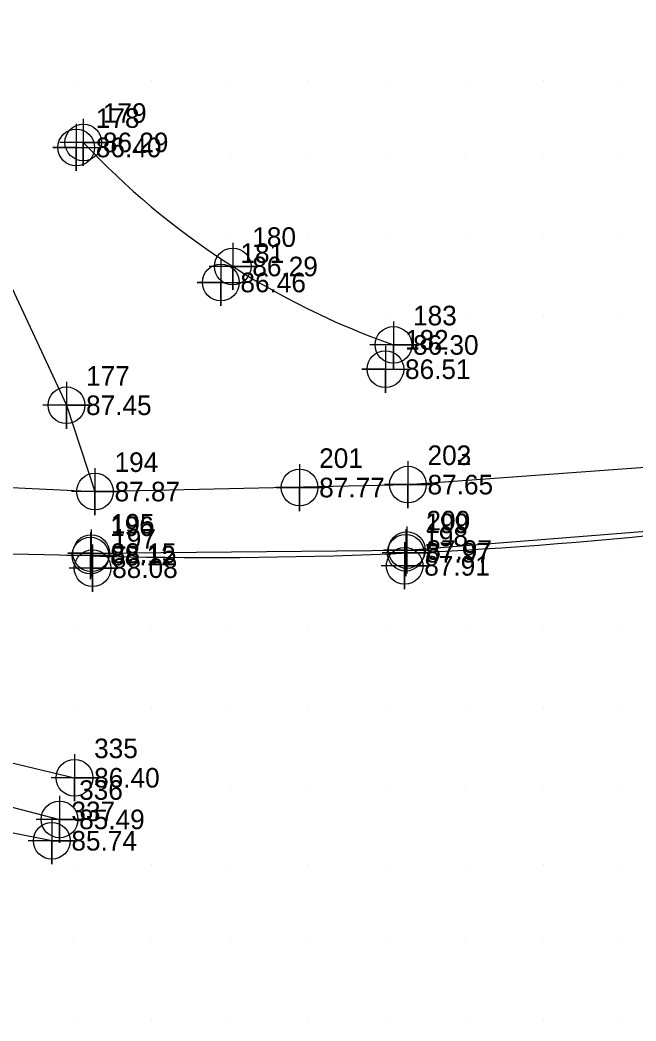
# Model space of a CAD drawing. Extents: x 1988140 to 1988766, y 249950 to 250250.
# Drawn here: x 1988293.2 to 1988371.8, y 249980 to 250107.7 of the extents above; entities that cross this region are included whole.
import ezdxf

# ---------------------------------------------------------------- set-up
doc = ezdxf.new("R2010")
doc.units = 0
for name, color, linetype in [('Exist DTM Breakline', 7, 'Continuous'), ('Exist DTM Breakline Cogo Elevation', 7, 'Continuous'), ('Exist DTM Breakline Cogo Number', 7, 'Continuous'), ('Exist DTM Breakline Cogo Point CELL', 7, 'Continuous'), ('Exist DTM Crownline', 7, 'Continuous'), ('Exist DTM Crownline Cogo Elevation', 7, 'Continuous'), ('Exist DTM Crownline Cogo Number', 7, 'Continuous'), ('Exist DTM Crownline Cogo Point CELL', 7, 'Continuous'), ('Exist DTM QL2 LIDAR Elevation Point', 7, 'Continuous'), ('Exist DTM Regular Point CELL', 7, 'Continuous'), ('Exist DTM Regular Point Cogo Elevation', 7, 'Continuous'), ('Exist DTM Regular Point Cogo Number', 7, 'Continuous'), ('Exist Roads EOP', 7, 'Continuous'), ('Exist Roads EOP Cogo Elevation', 7, 'Continuous'), ('Exist Roads EOP Cogo Number', 7, 'Continuous'), ('Exist Roads EOP Cogo Point CELL', 7, 'Continuous'), ('Exist Roads EOT', 7, 'Continuous'), ('Exist Roads EOT Cogo Elevation', 7, 'Continuous'), ('Exist Roads EOT Cogo Number', 7, 'Continuous'), ('Exist Roads EOT Cogo Point CELL', 7, 'Continuous')]:
    doc.layers.add(name, color=color, linetype=linetype)

msp = doc.modelspace()

# ---------------------------------------------------------------- linework, layer by layer
at = {"layer": 'Exist DTM Breakline'}
for points in [[(1988182.6136, 250035.5158), (1988182.9813, 250039.2171), (1988184.903, 250041.4732), (1988219.3187, 250033.3718), (1988254.9783, 250021.8401), (1988300.1272, 250011.0374)], [(1988185.4236, 250038.4105), (1988216.1279, 250028.952), (1988254.719, 250017.0301), (1988298.2155, 250005.7241)], [(1988297.226, 250002.9987), (1988255.3705, 250011.301), (1988214.5049, 250025.8516), (1988182.6136, 250035.5158)]]:
    msp.add_lwpolyline(points, dxfattribs=at)
at = {"layer": 'Exist DTM Breakline Cogo Point CELL'}
for points in [[(1988300.1272, 250014.0374), (1988300.1272, 250008.0374), (1988300.1272, 250011.0374), (1988303.1272, 250011.0374), (1988297.1272, 250011.0374)], [(1988298.2155, 250008.7241), (1988298.2155, 250002.7241), (1988298.2155, 250005.7241), (1988301.2155, 250005.7241), (1988295.2155, 250005.7241)], [(1988297.226, 250005.9987), (1988297.226, 249999.9987), (1988297.226, 250002.9987), (1988300.226, 250002.9987), (1988294.226, 250002.9987)]]:
    msp.add_lwpolyline(points, dxfattribs=at)
for centre in [(1988300.1272, 250011.0374), (1988298.2155, 250005.7241), (1988297.226, 250002.9987)]:
    msp.add_circle(centre, 2.344, dxfattribs=at)
at = {"layer": 'Exist DTM Crownline'}
for p, q in [((1988299.095, 250058.5693), (1988302.7374, 250047.561)), ((1988275.108, 250048.9258), (1988302.7374, 250047.561)), ((1988302.7374, 250047.561), (1988342.6848, 250048.4444))]:
    msp.add_line(p, q, dxfattribs=at)
for points in [[(1988218.8793, 250228.6049), (1988245.0113, 250174.1068), (1988268.5227, 250125.7119), (1988280.5459, 250098.297), (1988299.095, 250058.5693)], [(1988342.6848, 250048.4444), (1988378.1968, 250051.0543), (1988417.6158, 250057.1729)]]:
    msp.add_lwpolyline(points, dxfattribs=at)
at = {"layer": 'Exist DTM Crownline Cogo Point CELL'}
for points in [[(1988299.095, 250061.5693), (1988299.095, 250055.5693), (1988299.095, 250058.5693), (1988302.095, 250058.5693), (1988296.095, 250058.5693)], [(1988342.6848, 250051.4444), (1988342.6848, 250045.4444), (1988342.6848, 250048.4444), (1988345.6848, 250048.4444), (1988339.6848, 250048.4444)], [(1988302.7374, 250050.561), (1988302.7374, 250044.561), (1988302.7374, 250047.561), (1988305.7374, 250047.561), (1988299.7374, 250047.561)]]:
    msp.add_lwpolyline(points, dxfattribs=at)
for centre in [(1988299.095, 250058.5693), (1988342.6848, 250048.4444), (1988302.7374, 250047.561)]:
    msp.add_circle(centre, 2.344, dxfattribs=at)
at = {"layer": 'Exist DTM QL2 LIDAR Elevation Point'}
for p, q in [((1988300, 250100), (1988300, 250100)), ((1988310, 250100), (1988310, 250100)), ((1988320, 250100), (1988320, 250100)), ((1988330, 250100), (1988330, 250100)), ((1988340, 250100), (1988340, 250100)), ((1988350, 250100), (1988350, 250100)), ((1988360, 250100), (1988360, 250100)), ((1988370, 250100), (1988370, 250100)), ((1988310, 250090), (1988310, 250090)), ((1988320, 250090), (1988320, 250090)), ((1988330, 250090), (1988330, 250090)), ((1988340, 250090), (1988340, 250090)), ((1988350, 250090), (1988350, 250090)), ((1988360, 250090), (1988360, 250090)), ((1988370, 250090), (1988370, 250090)), ((1988320, 250080), (1988320, 250080)), ((1988330, 250080), (1988330, 250080)), ((1988340, 250080), (1988340, 250080)), ((1988350, 250080), (1988350, 250080)), ((1988360, 250080), (1988360, 250080)), ((1988370, 250080), (1988370, 250080)), ((1988340, 250070), (1988340, 250070)), ((1988350, 250070), (1988350, 250070)), ((1988360, 250070), (1988360, 250070)), ((1988370, 250070), (1988370, 250070)), ((1988370, 250040), (1988370, 250040)), ((1988300, 250030), (1988300, 250030)), ((1988310, 250030), (1988310, 250030)), ((1988320, 250030), (1988320, 250030)), ((1988330, 250030), (1988330, 250030)), ((1988340, 250030), (1988340, 250030)), ((1988350, 250030), (1988350, 250030)), ((1988360, 250030), (1988360, 250030)), ((1988370, 250030), (1988370, 250030)), ((1988300, 250020), (1988300, 250020)), ((1988310, 250020), (1988310, 250020)), ((1988320, 250020), (1988320, 250020)), ((1988330, 250020), (1988330, 250020)), ((1988340, 250020), (1988340, 250020)), ((1988350, 250020), (1988350, 250020)), ((1988360, 250020), (1988360, 250020)), ((1988370, 250020), (1988370, 250020)), ((1988310, 250010), (1988310, 250010)), ((1988320, 250010), (1988320, 250010)), ((1988330, 250010), (1988330, 250010)), ((1988340, 250010), (1988340, 250010)), ((1988350, 250010), (1988350, 250010)), ((1988360, 250010), (1988360, 250010)), ((1988370, 250010), (1988370, 250010)), ((1988300, 250000), (1988300, 250000)), ((1988310, 250000), (1988310, 250000)), ((1988320, 250000), (1988320, 250000)), ((1988330, 250000), (1988330, 250000)), ((1988340, 250000), (1988340, 250000)), ((1988350, 250000), (1988350, 250000)), ((1988360, 250000), (1988360, 250000)), ((1988370, 250000), (1988370, 250000)), ((1988300, 249990), (1988300, 249990)), ((1988310, 249990), (1988310, 249990)), ((1988320, 249990), (1988320, 249990)), ((1988330, 249990), (1988330, 249990)), ((1988340, 249990), (1988340, 249990)), ((1988350, 249990), (1988350, 249990)), ((1988360, 249990), (1988360, 249990)), ((1988370, 249990), (1988370, 249990)), ((1988300, 249980), (1988300, 249980)), ((1988310, 249980), (1988310, 249980)), ((1988320, 249980), (1988320, 249980)), ((1988330, 249980), (1988330, 249980)), ((1988340, 249980), (1988340, 249980)), ((1988350, 249980), (1988350, 249980)), ((1988360, 249980), (1988360, 249980)), ((1988370, 249980), (1988370, 249980))]:
    msp.add_line(p, q, dxfattribs=at)
at = {"layer": 'Exist DTM Regular Point CELL'}
for points in [[(1988342.2631, 250041.0837), (1988342.2631, 250035.0837), (1988342.2631, 250038.0837), (1988345.2631, 250038.0837), (1988339.2631, 250038.0837)], [(1988302.4323, 250040.7842), (1988302.4323, 250034.7842), (1988302.4323, 250037.7842), (1988305.4323, 250037.7842), (1988299.4323, 250037.7842)]]:
    msp.add_lwpolyline(points, dxfattribs=at)
for centre in [(1988302.4323, 250037.7842), (1988342.2631, 250038.0837)]:
    msp.add_circle(centre, 2.344, dxfattribs=at)
at = {"layer": 'Exist Roads EOP'}
msp.add_line((1988274.4694, 250039.9969), (1988302.1608, 250039.3839), dxfattribs=at)
for centre, radius, start, end in [((1988374.117, 250160.5027), 99.9372, 223.182371, 250.54548), ((1988317.1196, 250605.1999), 566.0511, 268.485592, 276.216725)]:
    msp.add_arc(centre, radius, start, end, dxfattribs=at)
at = {"layer": 'Exist Roads EOP Cogo Point CELL'}
for points in [[(1988301.2449, 250095.1134), (1988301.2449, 250089.1134), (1988301.2449, 250092.1134), (1988304.2449, 250092.1134), (1988298.2449, 250092.1134)], [(1988320.3152, 250079.2839), (1988320.3152, 250073.2839), (1988320.3152, 250076.2839), (1988323.3152, 250076.2839), (1988317.3152, 250076.2839)], [(1988340.8321, 250069.2713), (1988340.8321, 250063.2713), (1988340.8321, 250066.2713), (1988343.8321, 250066.2713), (1988337.8321, 250066.2713)], [(1988302.1608, 250042.3839), (1988302.1608, 250036.3839), (1988302.1608, 250039.3839), (1988305.1608, 250039.3839), (1988299.1608, 250039.3839)], [(1988342.3947, 250042.7526), (1988342.3947, 250036.7526), (1988342.3947, 250039.7526), (1988345.3947, 250039.7526), (1988339.3947, 250039.7526)]]:
    msp.add_lwpolyline(points, dxfattribs=at)
for centre in [(1988301.2449, 250092.1134), (1988320.3152, 250076.2839), (1988340.8321, 250066.2713), (1988302.1608, 250039.3839), (1988342.3947, 250039.7526)]:
    msp.add_circle(centre, 2.344, dxfattribs=at)
at = {"layer": 'Exist Roads EOT'}
for p, q in [((1988342.5427, 250040.1003), (1988378.4449, 250042.9134)), ((1988302.2604, 250039.6989), (1988342.5427, 250040.1003))]:
    msp.add_line(p, q, dxfattribs=at)
at = {"layer": 'Exist Roads EOT Cogo Point CELL'}
for points in [[(1988300.3426, 250094.4686), (1988300.3426, 250088.4686), (1988300.3426, 250091.4686), (1988297.3426, 250091.4686), (1988303.3426, 250091.4686)], [(1988318.7991, 250077.2412), (1988318.7991, 250071.2412), (1988318.7991, 250074.2412), (1988315.7991, 250074.2412), (1988321.7991, 250074.2412)], [(1988339.805, 250066.1773), (1988339.805, 250060.1773), (1988339.805, 250063.1773), (1988336.805, 250063.1773), (1988342.805, 250063.1773)], [(1988342.6848, 250051.4444), (1988342.6848, 250045.4444), (1988342.6848, 250048.4444), (1988339.6848, 250048.4444), (1988345.6848, 250048.4444)], [(1988328.8528, 250051.0722), (1988328.8528, 250045.0722), (1988328.8528, 250048.0722), (1988325.8528, 250048.0722), (1988331.8528, 250048.0722)], [(1988302.2604, 250042.6989), (1988302.2604, 250036.6989), (1988302.2604, 250039.6989), (1988299.2604, 250039.6989), (1988305.2604, 250039.6989)], [(1988342.5427, 250043.1003), (1988342.5427, 250037.1003), (1988342.5427, 250040.1003), (1988339.5427, 250040.1003), (1988345.5427, 250040.1003)]]:
    msp.add_lwpolyline(points, dxfattribs=at)
for centre in [(1988300.3426, 250091.4686), (1988318.7991, 250074.2412), (1988339.805, 250063.1773), (1988328.8528, 250048.0722), (1988342.6848, 250048.4444), (1988342.5427, 250040.1003), (1988302.2604, 250039.6989)]:
    msp.add_circle(centre, 2.344, dxfattribs=at)

# ---------------------------------------------------------------- texts
at = {"layer": 'Exist DTM Breakline Cogo Elevation'}
for s, p in [('86.40', (1988302.6272, 250009.7874)), ('85.49', (1988300.7155, 250004.4741)), ('85.74', (1988299.726, 250001.7487))]:
    msp.add_text(s, height=2.5, dxfattribs=at).set_placement(p)
at = {"layer": 'Exist DTM Breakline Cogo Number'}
for s, p in [('335', (1988302.6272, 250013.5374)), ('336', (1988300.7155, 250008.2241)), ('337', (1988299.726, 250005.4987))]:
    msp.add_text(s, height=2.5, dxfattribs=at).set_placement(p)
at = {"layer": 'Exist DTM Crownline Cogo Elevation'}
for s, p in [('87.45', (1988301.595, 250057.3193)), ('87.87', (1988305.2374, 250046.311)), ('87.65', (1988345.1848, 250047.1944))]:
    msp.add_text(s, height=2.5, dxfattribs=at).set_placement(p)
at = {"layer": 'Exist DTM Crownline Cogo Number'}
for s, p in [('177', (1988301.595, 250061.0693)), ('194', (1988305.2374, 250050.061)), ('203', (1988345.1848, 250050.9444))]:
    msp.add_text(s, height=2.5, dxfattribs=at).set_placement(p)
at = {"layer": 'Exist DTM Regular Point Cogo Elevation'}
for s, p in [('88.08', (1988304.9323, 250036.5342)), ('87.91', (1988344.7631, 250036.8337))]:
    msp.add_text(s, height=2.5, dxfattribs=at).set_placement(p)
at = {"layer": 'Exist DTM Regular Point Cogo Number'}
for s, p in [('197', (1988304.9323, 250040.2842)), ('198', (1988344.7631, 250040.5837))]:
    msp.add_text(s, height=2.5, dxfattribs=at).set_placement(p)
at = {"layer": 'Exist Roads EOP Cogo Elevation'}
for s, p in [('86.29', (1988303.7449, 250090.8634)), ('86.29', (1988322.8152, 250075.0339)), ('86.30', (1988343.3321, 250065.0213)), ('87.97', (1988344.8947, 250038.5026)), ('88.12', (1988304.6608, 250038.1339))]:
    msp.add_text(s, height=2.5, dxfattribs=at).set_placement(p)
at = {"layer": 'Exist Roads EOP Cogo Number'}
for s, p in [('179', (1988303.7449, 250094.6134)), ('180', (1988322.8152, 250078.7839)), ('183', (1988343.3321, 250068.7713)), ('196', (1988304.6608, 250041.8839)), ('199', (1988344.8947, 250042.2526))]:
    msp.add_text(s, height=2.5, dxfattribs=at).set_placement(p)
at = {"layer": 'Exist Roads EOT Cogo Elevation'}
for s, p in [('86.40', (1988302.8426, 250090.2186)), ('86.46', (1988321.2991, 250072.9912)), ('86.51', (1988342.305, 250061.9273)), ('87.77', (1988331.3528, 250046.8222)), ('87.65', (1988345.1848, 250047.1944)), ('87.97', (1988345.0427, 250038.8503)), ('88.15', (1988304.7604, 250038.4489))]:
    msp.add_text(s, height=2.5, dxfattribs=at).set_placement(p)
at = {"layer": 'Exist Roads EOT Cogo Number'}
for s, p in [('178', (1988302.8426, 250093.9686)), ('181', (1988321.2991, 250076.7412)), ('182', (1988342.305, 250065.6773)), ('201', (1988331.3528, 250050.5722)), ('202', (1988345.1848, 250050.9444)), ('200', (1988345.0427, 250042.6003)), ('195', (1988304.7604, 250042.1989))]:
    msp.add_text(s, height=2.5, dxfattribs=at).set_placement(p)

doc.saveas('drawing.dxf')
